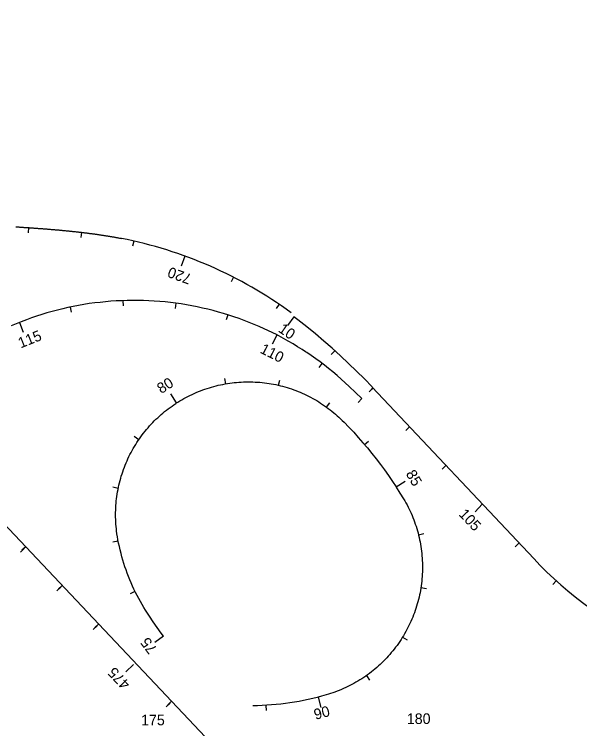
# Model space of a CAD drawing. Extents: x 448091 to 665917, y 1461380 to 1587607.
# Drawn here: x 572951 to 574015, y 1531839 to 1533184 of the extents above; entities that cross this region are included whole.
import ezdxf

# ---------------------------------------------------------------- set-up
doc = ezdxf.new("R2010")
doc.units = 0
doc.layers.add('TextShtNo', color=7, linetype='Continuous')
doc.layers.add('TextTitle', color=7, linetype='Continuous')

msp = doc.modelspace()

# ---------------------------------------------------------------- linework, layer by layer
at = {"layer": 'TextShtNo'}
for points in [[(574208.2, 1530872.3), (571463.6, 1533781.7)], [(573444.9, 1532580.8), (573421.5, 1532591.8), (573412.2, 1532595.9), (573402.9, 1532600), (573393.4, 1532603.8), (573383.8, 1532607.5), (573374.3, 1532611), (573364.6, 1532614.4), (573354.9, 1532617.5), (573345.2, 1532620.6), (573335.4, 1532623.4), (573325.5, 1532626.1), (573315.6, 1532628.6), (573305.7, 1532630.9), (573295.7, 1532633.1), (573285.7, 1532635.1), (573275.6, 1532636.8), (573265.5, 1532638.5), (573255.5, 1532640), (573245.3, 1532641.2), (573235.1, 1532642.3), (573225, 1532643.2), (573214.8, 1532644), (573204.6, 1532644.6), (573194.4, 1532644.9), (573184.2, 1532645.1), (573174, 1532645.2), (573163.8, 1532645), (573153.6, 1532644.7), (573143.4, 1532644.2), (573133.2, 1532643.5), (573123, 1532642.7), (573112.9, 1532641.6), (573102.7, 1532640.4), (573092.6, 1532639.1), (573082.5, 1532637.5), (573072.4, 1532635.7), (573062.4, 1532633.8), (573052.4, 1532631.7), (573042.5, 1532629.4), (573032.6, 1532627), (573022.7, 1532624.4), (573012.9, 1532621.6), (573003.1, 1532618.7), (572993.4, 1532615.5), (572983.7, 1532612.3), (572974.1, 1532608.8), (572964.6, 1532605.2), (572961.2, 1532603.8)], [(573624.6, 1532482.3), (573610.2, 1532497.3), (573595.4, 1532512.1), (573580.4, 1532526.6), (573565.1, 1532541.1), (573549.6, 1532555.1), (573533.8, 1532568.8), (573517.9, 1532582.4), (573501.6, 1532595.7), (573485.2, 1532608.5), (573477.6, 1532614.3)], [(572961.2, 1532603.8), (572955.1, 1532601.4), (572945.7, 1532597.4)], [(573499.5, 1532548.5), (573493.1, 1532552.6), (573484.5, 1532558), (573475.8, 1532563.3), (573466.9, 1532568.5), (573444.9, 1532580.8)], [(573605.1, 1532460.3), (573581.3, 1532483.2), (573573.8, 1532490.3), (573566.3, 1532497.1), (573558.6, 1532503.8), (573550.8, 1532510.5), (573542.9, 1532516.9), (573534.9, 1532523.2), (573526.7, 1532529.4), (573518.5, 1532535.4), (573510.2, 1532541.3), (573501.7, 1532547), (573499.5, 1532548.5)], [(573256.9, 1532452.2), (573259.2, 1532453.7), (573262.9, 1532456), (573266.6, 1532458.2), (573270.4, 1532460.3), (573274.3, 1532462.4), (573278.1, 1532464.5), (573282, 1532466.4), (573285.9, 1532468.3), (573289.9, 1532470.1), (573293.9, 1532471.9), (573297.9, 1532473.5), (573302, 1532475.1), (573306.1, 1532476.7), (573310.2, 1532478.2), (573314.3, 1532479.5), (573318.5, 1532480.9), (573322.7, 1532482.1), (573326.9, 1532483.3), (573331.1, 1532484.4), (573335.3, 1532485.4), (573339.6, 1532486.4), (573343.9, 1532487.2), (573348.2, 1532488.1), (573352.5, 1532488.8), (573356.8, 1532489.4), (573361.1, 1532490), (573365.4, 1532490.5), (573369.8, 1532490.9), (573374.1, 1532491.3), (573378.5, 1532491.5), (573382.8, 1532491.8), (573387.2, 1532491.9), (573391.6, 1532491.9), (573395.9, 1532491.9), (573400.3, 1532491.8), (573404.6, 1532491.6), (573409, 1532491.4), (573413.3, 1532491), (573417.7, 1532490.6), (573422, 1532490.1), (573426.4, 1532489.6), (573430.7, 1532488.9), (573435, 1532488.2), (573439.3, 1532487.4), (573443.6, 1532486.6), (573447.8, 1532485.6), (573452.1, 1532484.6), (573456.3, 1532483.5), (573460.5, 1532482.4), (573464.7, 1532481.2), (573468.8, 1532479.8), (573473, 1532478.5), (573477.1, 1532477), (573481.2, 1532475.5), (573485.3, 1532473.9), (573489.3, 1532472.3), (573493.3, 1532470.5), (573497.3, 1532468.7), (573501.2, 1532466.9), (573505.1, 1532464.9), (573509, 1532462.9), (573512.8, 1532460.8), (573516.6, 1532458.7), (573520.4, 1532456.5), (573524.1, 1532454.2), (573527.8, 1532451.9), (573531.4, 1532449.5), (573535, 1532447), (573538.6, 1532444.5), (573542.1, 1532441.9), (573545.6, 1532439.3), (573549, 1532436.5), (573552.4, 1532433.8), (573555.7, 1532431), (573559, 1532428), (573562.2, 1532425.1), (573565.4, 1532422.1), (573568.5, 1532419.1), (573571.8, 1532415.7), (573580.9, 1532406.4), (573590, 1532396.9), (573598.7, 1532387.2), (573607.4, 1532377.4), (573615.9, 1532367.4), (573624.2, 1532357.3), (573632.3, 1532347), (573640.2, 1532336.6), (573648, 1532326.1), (573655.5, 1532315.4), (573662.9, 1532304.5), (573669.9, 1532294)], [(573928.7, 1532159.1), (573624.7, 1532482.1)], [(573232, 1532013.2), (573228, 1532018.5), (573220.4, 1532029.2), (573212.9, 1532039.9), (573205.6, 1532050.8), (573198.5, 1532061.8), (573195.3, 1532066.9), (573192, 1532072.5), (573188.7, 1532078.2), (573185.6, 1532083.9), (573182.5, 1532089.7), (573179.5, 1532095.5), (573176.6, 1532101.5), (573173.9, 1532107.4), (573171.3, 1532113.4), (573168.7, 1532119.4), (573166.2, 1532125.5), (573163.9, 1532131.6), (573161.7, 1532137.7), (573159.6, 1532143.9), (573157.6, 1532150.1), (573155.6, 1532156.4), (573153.9, 1532162.7), (573152.2, 1532169), (573150.6, 1532175.4), (573149.2, 1532181.8), (573147.8, 1532188.2), (573146.5, 1532194.6), (573145.4, 1532201), (573145.4, 1532201), (573145.2, 1532202.3), (573144.6, 1532206.6), (573144, 1532211), (573143.5, 1532215.3), (573143.1, 1532219.6), (573142.7, 1532224), (573142.4, 1532228.3), (573142.2, 1532232.7), (573142.1, 1532237.1), (573142.1, 1532241.4), (573142.1, 1532245.8), (573142.2, 1532250.2), (573142.4, 1532254.5), (573142.6, 1532258.9), (573143, 1532263.2), (573143.4, 1532267.6), (573143.9, 1532271.9), (573144.4, 1532276.2), (573145.1, 1532280.5), (573145.8, 1532284.8), (573146.6, 1532289.1), (573147.4, 1532293.4), (573148.4, 1532297.7), (573149.4, 1532301.9), (573150.5, 1532306.1), (573151.6, 1532310.4), (573152.8, 1532314.5), (573154.1, 1532318.7), (573155.5, 1532322.8), (573157, 1532327), (573158.5, 1532331.1), (573160.1, 1532335.1), (573161.7, 1532339.2), (573163.5, 1532343.2), (573165.3, 1532347.1), (573167.1, 1532351.1), (573169.1, 1532355), (573171.1, 1532358.8), (573173.2, 1532362.7), (573175.3, 1532366.5), (573177.5, 1532370.3), (573179.8, 1532374), (573182.1, 1532377.7), (573184.5, 1532381.3), (573187, 1532384.9), (573189.5, 1532388.5), (573192.1, 1532392), (573194.7, 1532395.5), (573197.5, 1532398.9), (573200.2, 1532402.2), (573203, 1532405.6), (573206, 1532408.8), (573208.9, 1532412.1), (573211.9, 1532415.2), (573214.9, 1532418.3), (573218, 1532421.4), (573221.2, 1532424.4), (573224.4, 1532427.4), (573227.7, 1532430.3), (573231, 1532433.1), (573234.3, 1532435.9), (573237.7, 1532438.6), (573241.2, 1532441.3), (573244.7, 1532443.9), (573248.3, 1532446.4), (573251.9, 1532448.9), (573255.5, 1532451.3), (573256.9, 1532452.2)], [(573669.9, 1532294), (573670.1, 1532293.6), (573677.1, 1532282.6), (573683.9, 1532271.4), (573686.1, 1532267.8), (573688.2, 1532263.9), (573690.3, 1532260.1), (573692.3, 1532256.2), (573694.2, 1532252.3), (573696.1, 1532248.4), (573697.9, 1532244.4), (573699.7, 1532240.4), (573701.3, 1532236.4), (573702.9, 1532232.3), (573704.4, 1532228.2), (573705.9, 1532224.1), (573707.3, 1532220), (573708.6, 1532215.8), (573709.8, 1532211.6), (573711, 1532207.4), (573712.1, 1532203.2), (573713.1, 1532198.9), (573714, 1532194.7), (573714.9, 1532190.4), (573715.7, 1532186.1), (573716.4, 1532181.8), (573717, 1532177.5), (573717.6, 1532173.2), (573718.1, 1532168.8), (573718.5, 1532164.5), (573718.9, 1532160.1), (573719.1, 1532155.8), (573719.3, 1532151.4), (573719.4, 1532147.1), (573719.4, 1532142.7), (573719.4, 1532138.4), (573719.3, 1532134), (573719.1, 1532129.6), (573718.8, 1532125.3), (573718.5, 1532120.9), (573718, 1532116.6), (573717.6, 1532112.3), (573717, 1532107.9), (573716.3, 1532103.6), (573715.6, 1532099.3), (573714.8, 1532095), (573713.9, 1532090.7), (573713, 1532086.5), (573712, 1532082.3), (573710.9, 1532078), (573709.7, 1532073.8), (573708.4, 1532069.6), (573707.1, 1532065.5), (573705.7, 1532061.3), (573704.3, 1532057.2), (573702.7, 1532053.1), (573701.2, 1532049.1), (573699.5, 1532045), (573697.7, 1532041), (573695.9, 1532037.1), (573694, 1532033.1), (573692.1, 1532029.2), (573690.1, 1532025.4), (573688, 1532021.6), (573685.8, 1532017.7), (573683.6, 1532014), (573681.3, 1532010.3), (573679, 1532006.6), (573676.6, 1532002.9), (573674.1, 1531999.4), (573671.5, 1531995.8), (573668.9, 1531992.3), (573666.3, 1531988.8), (573663.6, 1531985.4), (573660.8, 1531982.1), (573658, 1531978.7), (573655.1, 1531975.5), (573652.1, 1531972.3), (573649.1, 1531969.1), (573646.1, 1531966), (573642.9, 1531963), (573639.8, 1531960), (573636.5, 1531957), (573633.3, 1531954.1), (573629.9, 1531951.3), (573626.6, 1531948.5), (573623.2, 1531945.8), (573619.7, 1531943.1), (573616.2, 1531940.6), (573612.6, 1531938), (573609, 1531935.6), (573605.4, 1531933.1), (573601.7, 1531930.8), (573598, 1531928.5), (573594.2, 1531926.3), (573590.4, 1531924.2), (573586.6, 1531922.1), (573582.7, 1531920.1), (573578.8, 1531918.1), (573574.9, 1531916.3), (573570.9, 1531914.5)], [(573570.9, 1531914.5), (573566.9, 1531912.7), (573562.9, 1531911.1), (573558.8, 1531909.5), (573554.7, 1531908), (573550.6, 1531906.5), (573546.5, 1531905.1), (573542.3, 1531903.8), (573538.1, 1531902.5), (573529.7, 1531900.2), (573523.3, 1531898.4)], [(573523.3, 1531898.4), (573521.3, 1531897.9), (573512.8, 1531895.8), (573504.3, 1531893.8), (573495.8, 1531892.1), (573487.2, 1531890.4), (573478.6, 1531888.9), (573470, 1531887.5), (573461.4, 1531886.3), (573452.7, 1531885.3), (573444, 1531884.4), (573435.3, 1531883.6), (573426.6, 1531883), (573417.9, 1531882.5), (573409.2, 1531882.2), (573400.4, 1531882.1)]]:
    msp.add_lwpolyline(points, dxfattribs=at)
for centre, radius, start, end in [((572999.2, 1531976.8), 800, 53.7672, 78.9072), ((574474.2, 1532673.7), 750, 223.3307, 266.2946)]:
    msp.add_arc(centre, radius, start, end, dxfattribs=at)
msp.add_spline([(572954.5, 1532783.9), (572957.2, 1532783.7), (572959.9, 1532783.5), (572962.6, 1532783.3), (572965.3, 1532783.1), (572968, 1532782.9), (572970.7, 1532782.7), (572973.4, 1532782.6), (572976.1, 1532782.4), (572978.7, 1532782.2), (572981.4, 1532782), (572984.1, 1532781.8), (572986.8, 1532781.6), (572989.5, 1532781.4), (572992.2, 1532781.2), (572994.9, 1532781), (572997.6, 1532780.8), (573000.3, 1532780.6), (573003, 1532780.4), (573005.7, 1532780.2), (573008.4, 1532780), (573011.1, 1532779.8), (573013.8, 1532779.6), (573016.5, 1532779.4), (573019.2, 1532779.1), (573021.9, 1532778.9), (573024.6, 1532778.7), (573027.3, 1532778.5), (573029.9, 1532778.2), (573032.6, 1532778), (573035.3, 1532777.8), (573038, 1532777.5), (573040.7, 1532777.3), (573043.4, 1532777), (573046.1, 1532776.8), (573048.8, 1532776.5), (573051.5, 1532776.2), (573054.2, 1532776), (573056.9, 1532775.7), (573059.5, 1532775.4), (573062.2, 1532775.1), (573064.9, 1532774.9), (573067.6, 1532774.6), (573070.3, 1532774.3), (573073, 1532774), (573075.7, 1532773.7), (573078.3, 1532773.3), (573081, 1532773), (573083.7, 1532772.7), (573086.4, 1532772.4), (573089.1, 1532772), (573091.8, 1532771.7), (573094.4, 1532771.3), (573097.1, 1532771), (573099.8, 1532770.6), (573102.5, 1532770.3), (573105.2, 1532769.9), (573107.8, 1532769.5), (573110.5, 1532769.1), (573113.2, 1532768.7), (573115.8, 1532768.3), (573118.5, 1532767.9), (573121.2, 1532767.5), (573123.9, 1532767.1), (573126.5, 1532766.6), (573129.2, 1532766.2), (573131.9, 1532765.8), (573134.5, 1532765.3), (573137.2, 1532764.8), (573139.8, 1532764.4), (573142.5, 1532763.9), (573145.2, 1532763.4), (573147.8, 1532762.9), (573150.5, 1532762.4), (573153.1, 1532761.9)], degree=3, dxfattribs=at)
at = {"layer": 'TextTitle'}
for p, q in [((572978, 1532782.2), (572977.3, 1532772.3)), ((573077.6, 1532773.4), (573076.4, 1532763.5)), ((573176.2, 1532757), (573174, 1532747.2)), ((573272.1, 1532728.8), (573265.3, 1532710)), ((573363.7, 1532689), (573359.2, 1532680.1)), ((573155.9, 1532644.7), (573156.1, 1532634.9)), ((573255.6, 1532639.8), (573254.2, 1532630.2)), ((573449.7, 1532638), (573444, 1532629.7)), ((573056.7, 1532632.5), (573058.7, 1532623.2)), ((573353.1, 1532618), (573350.3, 1532608.9)), ((573477.5, 1532614.2), (573465.5, 1532598.3)), ((572961.1, 1532603.7), (572968.4, 1532585.4)), ((573445.4, 1532579.9), (573436.5, 1532562.6)), ((573554.5, 1532550.5), (573547.9, 1532543.1)), ((573530, 1532526.7), (573524.1, 1532518.9)), ((573349.5, 1532488.3), (573347.8, 1532498.1)), ((573448.8, 1532485.4), (573451.2, 1532495.3)), ((573626, 1532480.5), (573619.4, 1532473.2)), ((573626.1, 1532480.6), (573622.8, 1532476.9)), ((573256.9, 1532452.2), (573245.8, 1532469.6)), ((573539.1, 1532444.1), (573545.1, 1532452.2)), ((573598.1, 1532453.1), (573605.1, 1532460.3)), ((573694.7, 1532407.5), (573688.1, 1532400.2)), ((573185.6, 1532382.9), (573176.7, 1532389)), ((573610.1, 1532374), (573617.8, 1532380.5)), ((573763.1, 1532334.5), (573756.6, 1532327.3)), ((573669.9, 1532294), (573686.6, 1532305)), ((573147, 1532291.4), (573136.8, 1532293.4)), ((573831.6, 1532261.4), (573818.5, 1532246.9)), ((573711.8, 1532203.7), (573721.9, 1532206.2)), ((572973, 1532181.5), (572965.8, 1532174.8)), ((573146.9, 1532192.1), (573137, 1532190.1)), ((573900.7, 1532188.5), (573894.1, 1532181.2)), ((572970.3, 1532178.3), (572963, 1532171.4)), ((573971, 1532117.4), (573964.4, 1532110.1)), ((573038.8, 1532105.4), (573031.5, 1532098.6)), ((573041.6, 1532108.8), (573034.4, 1532102)), ((573716.4, 1532104.5), (573726.7, 1532102.9)), ((573178.5, 1532097.5), (573169.4, 1532093)), ((573107.3, 1532032.6), (573100.1, 1532025.8)), ((573110.2, 1532036.1), (573103, 1532029.3)), ((573231.9, 1532013.1), (573215.9, 1532001.1)), ((573681.9, 1532011.3), (573690.8, 1532005.9)), ((573175.9, 1531959.8), (573161.3, 1531946.1)), ((573613.9, 1531938.9), (573619.9, 1531930.5)), ((573523.2, 1531898.3), (573528.3, 1531879.1)), ((573244.4, 1531887), (573237.1, 1531880.1)), ((573247.4, 1531890.6), (573240.3, 1531883.8)), ((573424.6, 1531882.8), (573425.1, 1531872.9))]:
    msp.add_line(p, q, dxfattribs=at)

# ---------------------------------------------------------------- texts
for s, rotation, p in [('720', 160.0566, (573286.7, 1532693.6)), ('10', 325.5839, (573446.6, 1532587.3)), ('115', 21.8015, (572963.4, 1532554.8)), ('110', 333.0913, (573412.2, 1532547.4)), ('80', 32.3272, (573227.9, 1532468.8)), ('85', 300.7188, (573687.3, 1532318.9)), ('105', 313.5102, (573786.4, 1532241.6)), ('75', 126.8355, (573221.2, 1531989.1)), ('475', 133.3503, (573170.8, 1531924.1)), ('90', 15.0491, (573518.1, 1531855.5)), ('175', 0.2236, (573190, 1531845.2)), ('180', 0.2236, (573690, 1531847.7))]:
    msp.add_text(s, height=20, rotation=rotation, dxfattribs=at).set_placement(p)

doc.saveas('drawing.dxf')
